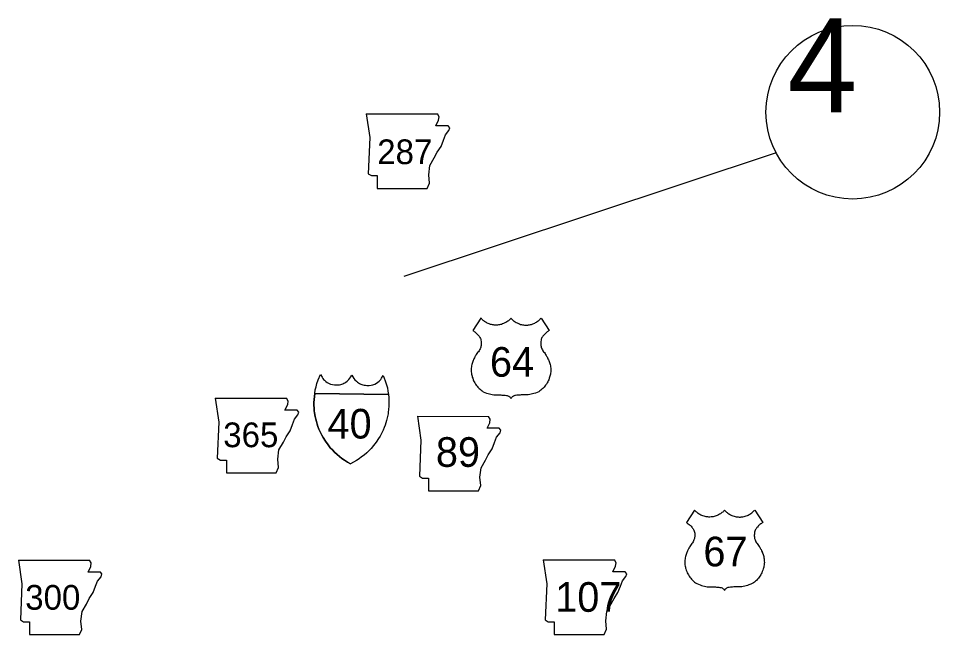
# Model space of a CAD drawing. Extents: x -819161 to 80911, y -6604 to 768454.
# Drawn here: x 43491 to 45459, y -3743 to -2427 of the extents above; entities that cross this region are included whole.
import ezdxf

# ---------------------------------------------------------------- set-up
doc = ezdxf.new("R2010")
doc.units = 0
for name, color, linetype in [('21', 7, 'Continuous'), ('22', 7, 'Continuous'), ('DSN_DRFT_Common-Line', 7, 'Continuous'), ('Level 21', 7, 'Continuous'), ('Level 22', 7, 'Continuous'), ('Level 23', 7, 'Continuous')]:
    doc.layers.add(name, color=color, linetype=linetype)

msp = doc.modelspace()

# ---------------------------------------------------------------- linework, layer by layer
at = {"layer": '21'}
for p, q in [((43490.5, -3584.4), (43498.1, -3635.2)), ((43639.4, -3609.8), (43645.3, -3598)), ((43646.2, -3590.3), (43642.6, -3584.5)), ((43645.3, -3598), (43646.2, -3590.3)), ((44611.8, -3584), (44619.5, -3634.8)), ((44760.7, -3609.4), (44766.6, -3597.6)), ((44767.5, -3589.9), (44764, -3584.1)), ((44766.6, -3597.6), (44767.5, -3589.9)), ((43665.6, -3609.8), (43639.4, -3609.8)), ((43659.7, -3629.3), (43667.3, -3620)), ((43669, -3614), (43665.6, -3609.8)), ((43667.3, -3620), (43669, -3614)), ((44786.9, -3609.4), (44760.7, -3609.4)), ((44781, -3628.9), (44788.6, -3619.6)), ((44790.3, -3613.6), (44786.9, -3609.4)), ((44788.6, -3619.6), (44790.3, -3613.6)), ((43498.1, -3635.2), (43494.7, -3712.2)), ((43650.4, -3653.8), (43655.5, -3640.3)), ((43655.5, -3640.3), (43659.7, -3629.3)), ((44619.5, -3634.8), (44616.1, -3711.8)), ((44771.7, -3653.4), (44776.8, -3639.9)), ((44776.8, -3639.9), (44781, -3628.9)), ((43641.9, -3666.5), (43650.4, -3653.8)), ((44763.3, -3666.1), (44771.7, -3653.4)), ((43626.7, -3694.4), (43636, -3678.3)), ((43636, -3678.3), (43641.9, -3666.5)), ((44748, -3694), (44757.3, -3677.9)), ((44757.3, -3677.9), (44763.3, -3666.1)), ((43624.2, -3714.7), (43626.7, -3694.4)), ((44745.5, -3714.3), (44748, -3694)), ((43494.7, -3712.2), (43501.5, -3716.4)), ((43501.5, -3716.4), (43514.2, -3716.4)), ((43514.2, -3716.4), (43514.2, -3743.5)), ((43625.9, -3732.5), (43624.2, -3714.7)), ((44616.1, -3711.8), (44622.8, -3716)), ((44622.8, -3716), (44635.5, -3716)), ((44635.5, -3716), (44635.5, -3743.1)), ((44747.2, -3732.1), (44745.5, -3714.3)), ((43620.8, -3743.5), (43625.9, -3732.5)), ((44742.1, -3743.1), (44747.2, -3732.1)), ((43514.2, -3743.5), (43620.8, -3743.5)), ((44635.5, -3743.1), (44742.1, -3743.1))]:
    msp.add_line(p, q, dxfattribs=at)
for points in [[(43490.5, -3584.4), (43642.6, -3584.5)], [(44611.8, -3584), (44764, -3584.1)]]:
    msp.add_lwpolyline(points, dxfattribs=at)
at = {"layer": '22'}
for points in [[(44999.4, -3477.5), (44998.1, -3478.9), (44996.9, -3480.2), (44995.4, -3481.6), (44993.9, -3482.9), (44992.4, -3484), (44990.6, -3485.3), (44988.7, -3486.5), (44986.5, -3487.7), (44983.7, -3489), (44981.5, -3489.9), (44979.1, -3490.6), (44976.9, -3491.2), (44974.8, -3491.6), (44972.6, -3492), (44970.7, -3492.2), (44967.9, -3492.3), (44965.7, -3492.3), (44963.8, -3492.2), (44962, -3492), (44960.1, -3491.7), (44957.8, -3491.2), (44955.6, -3490.7), (44953, -3489.8), (44950.8, -3488.9), (44948.7, -3488), (44946.9, -3487), (44945.2, -3486), (44943.2, -3484.8), (44941.5, -3483.5), (44940, -3482.2), (44938.7, -3481.1), (44937.4, -3479.8), (44936.1, -3478.5), (44935.1, -3477.3), (44917.8, -3504.1), (44919, -3504.8), (44920.5, -3505.8), (44921.9, -3506.8), (44923.7, -3508.2), (44925.2, -3509.5), (44926.6, -3510.7), (44927.9, -3512.1), (44929.3, -3513.6), (44930.2, -3514.8), (44931.2, -3516.1), (44932.2, -3517.4), (44933.2, -3518.9), (44934, -3520.6), (44934.7, -3522.7), (44935.2, -3524.7), (44935.6, -3526.9), (44935.8, -3529), (44935.9, -3531), (44935.8, -3532.8), (44935.7, -3534.3), (44935.5, -3536.1), (44935.1, -3537.9), (44934.7, -3539.7), (44934.1, -3541.3), (44933.4, -3543.2), (44932.3, -3545.5), (44931.1, -3547.4), (44929.7, -3549.1), (44928.1, -3551.2), (44926.7, -3553.1), (44925.4, -3555), (44924.2, -3556.9), (44923.2, -3558.6), (44922.4, -3560.2), (44921.4, -3562), (44920.3, -3564.2), (44919.4, -3566.4), (44918.8, -3567.9), (44918, -3570), (44917.1, -3572.5), (44916.5, -3574.5), (44915.8, -3576.8), (44915.3, -3579.4), (44914.9, -3581.8), (44914.6, -3584.2), (44914.4, -3586.9), (44914.4, -3589.4), (44914.5, -3591.8), (44914.8, -3594.7), (44915.3, -3597.4), (44915.7, -3599.5), (44916.2, -3601.3), (44916.8, -3603.3), (44917.6, -3605.9), (44918.7, -3608.9), (44919.7, -3611.2), (44920.9, -3613.6), (44922.1, -3615.8), (44923.7, -3618.5), (44925.4, -3620.9), (44927.1, -3623), (44928.9, -3625.1), (44931.3, -3627.6), (44933.3, -3629.5), (44935.4, -3631.3)], [(44999.4, -3477.5), (45000.8, -3478.9), (45002, -3480.2), (45003.4, -3481.6), (45005, -3482.9), (45006.5, -3484), (45008.3, -3485.3), (45010.2, -3486.5), (45012.4, -3487.7), (45015.2, -3489), (45017.4, -3489.9), (45019.8, -3490.6), (45022, -3491.2), (45024.1, -3491.6), (45026.2, -3492), (45028.2, -3492.2), (45030.9, -3492.3), (45033.2, -3492.3), (45035.1, -3492.2), (45036.9, -3492), (45038.8, -3491.7), (45041.1, -3491.2), (45043.3, -3490.7), (45045.9, -3489.8), (45048.1, -3488.9), (45050.1, -3488), (45052, -3487), (45053.7, -3486), (45055.6, -3484.8), (45057.4, -3483.5), (45058.9, -3482.2), (45060.2, -3481.1), (45061.5, -3479.8), (45062.8, -3478.5), (45063.8, -3477.3), (45081.1, -3504.1), (45079.9, -3504.8), (45078.4, -3505.8), (45077, -3506.8), (45075.1, -3508.2), (45073.6, -3509.5), (45072.3, -3510.7), (45071, -3512.1), (45069.6, -3513.6), (45068.6, -3514.8), (45067.7, -3516.1), (45066.7, -3517.4), (45065.7, -3518.9), (45064.8, -3520.6), (45064.2, -3522.7), (45063.6, -3524.7), (45063.3, -3526.9), (45063.1, -3529), (45063, -3531), (45063, -3532.8), (45063.2, -3534.3), (45063.4, -3536.1), (45063.7, -3537.9), (45064.2, -3539.7), (45064.7, -3541.3), (45065.5, -3543.2), (45066.6, -3545.5), (45067.7, -3547.4), (45069.1, -3549.1), (45070.8, -3551.2), (45072.2, -3553.1), (45073.5, -3555), (45074.7, -3556.9), (45075.6, -3558.6), (45076.5, -3560.2), (45077.5, -3562), (45078.5, -3564.2), (45079.5, -3566.4), (45080.1, -3567.9), (45080.9, -3570), (45081.7, -3572.5), (45082.4, -3574.5), (45083, -3576.8), (45083.6, -3579.4), (45084, -3581.8), (45084.3, -3584.2), (45084.4, -3586.9), (45084.5, -3589.4), (45084.3, -3591.8), (45084, -3594.7), (45083.6, -3597.4), (45083.1, -3599.5), (45082.7, -3601.3), (45082.1, -3603.3), (45081.3, -3605.9), (45080.1, -3608.9), (45079.2, -3611.2), (45078, -3613.6), (45076.8, -3615.8), (45075.1, -3618.5), (45073.5, -3620.9), (45071.8, -3623), (45070, -3625.1), (45067.6, -3627.6), (45065.5, -3629.5), (45063.5, -3631.3)], [(44935.4, -3631.3), (44937.6, -3632.9), (44940.2, -3634.6), (44943.5, -3636.1), (44947.3, -3637.5), (44950.4, -3638.6), (44953.3, -3639.3), (44956.4, -3640.1), (44959.4, -3640.6), (44962.6, -3641.1), (44966.7, -3641.4), (44969.8, -3641.5), (44972.4, -3641.5), (44975, -3641.5), (44977.6, -3641.6), (44980, -3641.7), (44982.2, -3641.9), (44984.3, -3642.1), (44987, -3642.3), (44989.6, -3642.7), (44991.2, -3642.9), (44992.5, -3643.1), (44994, -3643.8), (44994.9, -3644.3), (44995.7, -3644.8), (44996.8, -3645.7), (44997.8, -3646.7), (44998.7, -3647.8), (44999.4, -3649.1)], [(45063.5, -3631.3), (45061.3, -3632.9), (45058.7, -3634.6), (45055.4, -3636.1), (45051.6, -3637.5), (45048.4, -3638.6), (45045.6, -3639.3), (45042.4, -3640.1), (45039.5, -3640.6), (45036.2, -3641.1), (45032.2, -3641.4), (45029.1, -3641.5), (45026.5, -3641.5), (45023.9, -3641.5), (45021.3, -3641.6), (45018.9, -3641.7), (45016.7, -3641.9), (45014.6, -3642.1), (45011.9, -3642.3), (45009.3, -3642.7), (45007.7, -3642.9), (45006.4, -3643.1), (45004.8, -3643.8), (45003.9, -3644.3), (45003.2, -3644.8), (45002.1, -3645.7), (45001, -3646.7), (45000.2, -3647.8), (44999.4, -3649.1)]]:
    msp.add_lwpolyline(points, dxfattribs=at)
at = {"layer": 'DSN_DRFT_Common-Line'}
msp.add_lwpolyline([(45109.4, -2714.2), (44314.2, -2978.5)], dxfattribs=at)
msp.add_circle((45273.4, -2627.3), 185.5, dxfattribs=at)
at = {"layer": 'Level 21'}
for p, q in [((44233.7, -2631), (44241.3, -2681.7)), ((44389.3, -2636.9), (44385.8, -2631.1)), ((44388.5, -2644.5), (44389.3, -2636.9)), ((44382.6, -2656.4), (44388.5, -2644.5)), ((44408.8, -2656.4), (44382.6, -2656.4)), ((44412.2, -2660.6), (44408.8, -2656.4)), ((44398.6, -2686.8), (44402.9, -2675.8)), ((44402.9, -2675.8), (44410.5, -2666.5)), ((44410.5, -2666.5), (44412.2, -2660.6)), ((44241.3, -2681.7), (44237.9, -2758.7)), ((44393.6, -2700.4), (44398.6, -2686.8)), ((44379.2, -2724.9), (44385.1, -2713)), ((44385.1, -2713), (44393.6, -2700.4)), ((44369.9, -2741), (44379.2, -2724.9)), ((44367.3, -2761.3), (44369.9, -2741)), ((44237.9, -2758.7), (44244.7, -2762.9)), ((44244.7, -2762.9), (44257.4, -2762.9)), ((44257.4, -2762.9), (44257.4, -2790)), ((44369, -2779), (44367.3, -2761.3)), ((44257.4, -2790), (44363.9, -2790)), ((44363.9, -2790), (44369, -2779)), ((43911.2, -3238.5), (43918.8, -3289.3)), ((44066.8, -3244.5), (44063.3, -3238.6)), ((44066, -3252.1), (44066.8, -3244.5)), ((44060, -3263.9), (44066, -3252.1)), ((44086.3, -3263.9), (44060, -3263.9)), ((44089.6, -3268.1), (44086.3, -3263.9)), ((44076.1, -3294.4), (44080.3, -3283.4)), ((44080.3, -3283.4), (44087.9, -3274.1)), ((44087.9, -3274.1), (44089.6, -3268.1)), ((44343, -3277.1), (44350.6, -3327.9)), ((44498.7, -3283.1), (44495.1, -3277.2)), ((44497.8, -3290.7), (44498.7, -3283.1)), ((43918.8, -3289.3), (43915.4, -3366.3)), ((44071, -3307.9), (44076.1, -3294.4)), ((44491.9, -3302.5), (44497.8, -3290.7)), ((44518.1, -3302.5), (44491.9, -3302.5)), ((44521.5, -3306.8), (44518.1, -3302.5)), ((44519.8, -3312.7), (44521.5, -3306.8)), ((44056.6, -3332.4), (44062.6, -3320.6)), ((44062.6, -3320.6), (44071, -3307.9)), ((44508, -3333), (44512.2, -3322)), ((44512.2, -3322), (44519.8, -3312.7)), ((44047.3, -3348.5), (44056.6, -3332.4)), ((44350.6, -3327.9), (44347.2, -3404.9)), ((44502.9, -3346.5), (44508, -3333)), ((44044.8, -3368.8), (44047.3, -3348.5)), ((44488.5, -3371), (44494.4, -3359.2)), ((44494.4, -3359.2), (44502.9, -3346.5)), ((43915.4, -3366.3), (43922.2, -3370.5)), ((43922.2, -3370.5), (43934.8, -3370.5)), ((43934.8, -3370.5), (43934.8, -3397.6)), ((44046.5, -3386.6), (44044.8, -3368.8)), ((44479.2, -3387.1), (44488.5, -3371)), ((43934.8, -3397.6), (44041.4, -3397.6)), ((44041.4, -3397.6), (44046.5, -3386.6)), ((44347.2, -3404.9), (44354, -3409.1)), ((44476.7, -3407.4), (44479.2, -3387.1)), ((44354, -3409.1), (44366.7, -3409.1)), ((44366.7, -3409.1), (44366.7, -3436.2)), ((44478.3, -3425.2), (44476.7, -3407.4)), ((44366.7, -3436.2), (44473.3, -3436.2)), ((44473.3, -3436.2), (44478.3, -3425.2))]:
    msp.add_line(p, q, dxfattribs=at)
for points in [[(44233.7, -2631), (44385.8, -2631.1)], [(43911.2, -3238.5), (44063.3, -3238.6)], [(44343, -3277.1), (44495.1, -3277.2)]]:
    msp.add_lwpolyline(points, dxfattribs=at)
at = {"layer": 'Level 22'}
for points in [[(44543, -3067.4), (44541.7, -3068.8), (44540.5, -3070.1), (44539, -3071.5), (44537.5, -3072.8), (44536, -3074), (44534.2, -3075.2), (44532.3, -3076.4), (44530.1, -3077.6), (44527.3, -3078.9), (44525.1, -3079.8), (44522.7, -3080.6), (44520.5, -3081.1), (44518.4, -3081.6), (44516.2, -3081.9), (44514.3, -3082.1), (44511.5, -3082.2), (44509.3, -3082.2), (44507.4, -3082.1), (44505.6, -3081.9), (44503.7, -3081.6), (44501.4, -3081.1), (44499.2, -3080.6), (44496.6, -3079.7), (44494.4, -3078.8), (44492.3, -3077.9), (44490.5, -3076.9), (44488.8, -3075.9), (44486.8, -3074.7), (44485.1, -3073.4), (44483.6, -3072.1), (44482.3, -3071), (44481, -3069.8), (44479.7, -3068.4), (44478.7, -3067.2), (44461.4, -3094), (44462.6, -3094.7), (44464.1, -3095.7), (44465.5, -3096.7), (44467.3, -3098.1), (44468.8, -3099.4), (44470.1, -3100.6), (44471.5, -3102), (44472.9, -3103.5), (44473.8, -3104.7), (44474.8, -3106), (44475.8, -3107.3), (44476.8, -3108.8), (44477.6, -3110.5), (44478.3, -3112.6), (44478.8, -3114.6), (44479.2, -3116.9), (44479.4, -3118.9), (44479.5, -3120.9), (44479.4, -3122.7), (44479.3, -3124.2), (44479.1, -3126.1), (44478.7, -3127.8), (44478.3, -3129.6), (44477.7, -3131.3), (44477, -3133.1), (44475.9, -3135.4), (44474.7, -3137.3), (44473.3, -3139), (44471.7, -3141.1), (44470.3, -3143), (44469, -3145), (44467.8, -3146.8), (44466.8, -3148.5), (44466, -3150.1), (44465, -3151.9), (44463.9, -3154.1), (44463, -3156.3), (44462.3, -3157.9), (44461.6, -3159.9), (44460.7, -3162.4), (44460.1, -3164.5), (44459.4, -3166.7), (44458.9, -3169.3), (44458.5, -3171.7), (44458.2, -3174.1), (44458, -3176.8), (44458, -3179.3), (44458.1, -3181.7), (44458.4, -3184.6), (44458.9, -3187.3), (44459.3, -3189.4), (44459.8, -3191.2), (44460.4, -3193.2), (44461.2, -3195.8), (44462.3, -3198.9), (44463.3, -3201.1), (44464.5, -3203.5), (44465.7, -3205.8), (44467.3, -3208.4), (44469, -3210.8), (44470.7, -3212.9), (44472.5, -3215.1), (44474.9, -3217.5), (44476.9, -3219.4), (44479, -3221.2)], [(44543, -3067.4), (44544.4, -3068.8), (44545.6, -3070.1), (44547, -3071.5), (44548.6, -3072.8), (44550.1, -3074), (44551.9, -3075.2), (44553.8, -3076.4), (44556, -3077.6), (44558.8, -3078.9), (44561, -3079.8), (44563.4, -3080.6), (44565.6, -3081.1), (44567.7, -3081.6), (44569.8, -3081.9), (44571.8, -3082.1), (44574.5, -3082.2), (44576.8, -3082.2), (44578.7, -3082.1), (44580.5, -3081.9), (44582.4, -3081.6), (44584.7, -3081.1), (44586.9, -3080.6), (44589.5, -3079.7), (44591.7, -3078.8), (44593.7, -3077.9), (44595.6, -3076.9), (44597.3, -3075.9), (44599.2, -3074.7), (44601, -3073.4), (44602.5, -3072.1), (44603.8, -3071), (44605.1, -3069.8), (44606.3, -3068.4), (44607.4, -3067.2), (44624.7, -3094), (44623.5, -3094.7), (44622, -3095.7), (44620.6, -3096.7), (44618.7, -3098.1), (44617.2, -3099.4), (44615.9, -3100.6), (44614.6, -3102), (44613.2, -3103.5), (44612.2, -3104.7), (44611.3, -3106), (44610.3, -3107.3), (44609.3, -3108.8), (44608.4, -3110.5), (44607.8, -3112.6), (44607.2, -3114.6), (44606.9, -3116.9), (44606.7, -3118.9), (44606.6, -3120.9), (44606.6, -3122.7), (44606.8, -3124.2), (44607, -3126.1), (44607.3, -3127.8), (44607.8, -3129.6), (44608.3, -3131.3), (44609.1, -3133.1), (44610.2, -3135.4), (44611.3, -3137.3), (44612.7, -3139), (44614.4, -3141.1), (44615.8, -3143), (44617.1, -3145), (44618.3, -3146.8), (44619.2, -3148.5), (44620.1, -3150.1), (44621.1, -3151.9), (44622.1, -3154.1), (44623.1, -3156.3), (44623.7, -3157.9), (44624.5, -3159.9), (44625.3, -3162.4), (44626, -3164.5), (44626.6, -3166.7), (44627.2, -3169.3), (44627.6, -3171.7), (44627.9, -3174.1), (44628, -3176.8), (44628.1, -3179.3), (44627.9, -3181.7), (44627.6, -3184.6), (44627.2, -3187.3), (44626.7, -3189.4), (44626.3, -3191.2), (44625.7, -3193.2), (44624.9, -3195.8), (44623.7, -3198.9), (44622.8, -3201.1), (44621.6, -3203.5), (44620.4, -3205.8), (44618.7, -3208.4), (44617, -3210.8), (44615.4, -3212.9), (44613.6, -3215.1), (44611.2, -3217.5), (44609.1, -3219.4), (44607.1, -3221.2)], [(44479, -3221.2), (44481.2, -3222.8), (44483.8, -3224.5), (44487.1, -3226), (44490.9, -3227.4), (44494, -3228.5), (44496.9, -3229.2), (44500, -3230), (44503, -3230.5), (44506.2, -3231), (44510.3, -3231.3), (44513.4, -3231.4), (44516, -3231.4), (44518.6, -3231.4), (44521.2, -3231.5), (44523.6, -3231.6), (44525.8, -3231.8), (44527.9, -3232), (44530.5, -3232.2), (44533.2, -3232.6), (44534.8, -3232.8), (44536.1, -3233), (44537.6, -3233.7), (44538.5, -3234.2), (44539.3, -3234.7), (44540.4, -3235.6), (44541.4, -3236.6), (44542.3, -3237.7), (44543, -3239)], [(44607.1, -3221.2), (44604.9, -3222.8), (44602.3, -3224.5), (44599, -3226), (44595.2, -3227.4), (44592, -3228.5), (44589.2, -3229.2), (44586, -3230), (44583.1, -3230.5), (44579.8, -3231), (44575.8, -3231.3), (44572.7, -3231.4), (44570, -3231.4), (44567.5, -3231.4), (44564.9, -3231.5), (44562.4, -3231.6), (44560.3, -3231.8), (44558.2, -3232), (44555.5, -3232.2), (44552.9, -3232.6), (44551.3, -3232.8), (44550, -3233), (44548.4, -3233.7), (44547.5, -3234.2), (44546.8, -3234.7), (44545.7, -3235.6), (44544.6, -3236.6), (44543.8, -3237.7), (44543, -3239)]]:
    msp.add_lwpolyline(points, dxfattribs=at)
at = {"layer": 'Level 23'}
msp.add_line((44123.8, -3228), (44281.1, -3230.6), dxfattribs=at)
for points in [[(44123.7, -3228), (44124.9, -3220.8), (44126.5, -3214), (44128.5, -3207.3), (44131.3, -3198.8), (44136.1, -3187.7), (44139.6, -3193.7), (44141.1, -3196.2), (44142.6, -3198.2), (44144.5, -3200.1), (44147.3, -3202.6), (44150.2, -3204.7), (44153.4, -3206.5), (44157.5, -3208.1), (44161.5, -3209.2), (44165.8, -3209.8), (44170.3, -3210.1), (44173.7, -3209.8), (44176.4, -3209.6), (44179.3, -3209), (44183.4, -3207.5), (44186, -3206.4), (44188.3, -3205.3), (44190.4, -3203.9), (44193, -3201.9), (44196.5, -3198.7), (44198.9, -3195.9), (44200.9, -3192.7), (44203.1, -3189)], [(44123.7, -3228), (44124.9, -3220.8), (44126.5, -3214), (44128.5, -3207.3), (44131.3, -3198.8), (44136.1, -3187.7), (44139.6, -3193.7), (44141.1, -3196.2), (44142.6, -3198.2), (44144.5, -3200.1), (44147.3, -3202.6), (44150.2, -3204.7), (44153.4, -3206.5), (44157.5, -3208.1), (44161.5, -3209.2), (44165.8, -3209.8), (44170.3, -3210.1), (44173.7, -3209.8), (44176.4, -3209.6), (44179.3, -3209), (44183.4, -3207.5), (44186, -3206.4), (44188.3, -3205.3), (44190.4, -3203.9), (44193, -3201.9), (44196.5, -3198.7), (44198.9, -3195.9), (44200.9, -3192.7), (44203.1, -3189)], [(44203.1, -3189), (44205.2, -3192.8), (44207.1, -3196), (44209.4, -3198.9), (44212.7, -3202.3), (44215.3, -3204.3), (44217.4, -3205.8), (44219.6, -3207), (44222.2, -3208.2), (44226.3, -3209.7), (44229.2, -3210.4), (44231.9, -3210.8), (44235.2, -3211.1), (44239.7, -3211), (44244.1, -3210.5), (44248.1, -3209.6), (44252.2, -3208.1), (44255.5, -3206.4), (44258.4, -3204.3), (44261.3, -3202), (44263.2, -3200.1), (44264.8, -3198.2), (44266.4, -3195.7), (44270.1, -3189.9), (44274.5, -3201.1), (44277.1, -3209.7), (44278.9, -3216.4), (44280.2, -3223.3), (44281.2, -3230.6)], [(44203.1, -3189), (44205.2, -3192.8), (44207.1, -3196), (44209.4, -3198.9), (44212.7, -3202.3), (44215.3, -3204.3), (44217.4, -3205.8), (44219.6, -3207), (44222.2, -3208.2), (44226.3, -3209.7), (44229.2, -3210.4), (44231.9, -3210.8), (44235.2, -3211.1), (44239.7, -3211), (44244.1, -3210.5), (44248.1, -3209.6), (44252.2, -3208.1), (44255.5, -3206.4), (44258.4, -3204.3), (44261.3, -3202), (44263.2, -3200.1), (44264.8, -3198.2), (44266.4, -3195.7), (44270.1, -3189.9), (44274.5, -3201.1), (44277.1, -3209.7), (44278.9, -3216.4), (44280.2, -3223.3), (44281.2, -3230.6)], [(44200.1, -3378.3), (44193.9, -3374.9), (44187.4, -3370.8), (44181.9, -3367.1), (44176.9, -3363.3), (44171.7, -3358.9), (44166, -3353.7), (44161.3, -3349), (44157, -3344.2), (44152.2, -3338.3), (44146.4, -3330.2), (44141.7, -3322.7), (44138.7, -3317.3), (44135.7, -3311.4), (44132.8, -3304.7), (44130.6, -3299), (44128.8, -3293.7), (44127.2, -3288.4), (44125.9, -3283.2), (44124.6, -3277.6), (44123.3, -3269.6), (44122.8, -3265.4), (44122.3, -3259.7), (44122.1, -3253.1), (44122.1, -3247.5), (44122.3, -3241.2), (44122.9, -3234.5), (44123.8, -3228)], [(44123.8, -3228), (44122.9, -3234.5), (44122.3, -3241.2), (44122.1, -3247.5), (44122.1, -3253.1), (44122.3, -3259.7), (44122.8, -3265.4), (44123.3, -3269.6), (44124.6, -3277.6), (44125.9, -3283.2), (44127.2, -3288.4), (44128.8, -3293.7), (44130.6, -3299), (44132.8, -3304.7), (44135.7, -3311.4), (44138.7, -3317.3), (44141.7, -3322.7), (44146.4, -3330.2), (44152.2, -3338.3), (44157, -3344.2), (44161.3, -3349), (44166, -3353.7), (44171.7, -3358.9), (44176.9, -3363.3), (44181.9, -3367.1), (44187.4, -3370.8), (44193.9, -3374.9), (44200.1, -3378.3)], [(44281.2, -3230.6), (44123.7, -3228)], [(44281.2, -3230.6), (44123.7, -3228)], [(44281.1, -3230.6), (44281.8, -3237), (44282.1, -3243.8), (44282.2, -3250), (44282.1, -3255.7), (44281.6, -3262.3), (44280.9, -3267.9), (44280.3, -3272.1), (44278.7, -3280.1), (44277.3, -3285.7), (44275.8, -3290.7), (44274, -3296), (44272.1, -3301.2), (44269.7, -3306.9), (44266.5, -3313.5), (44263.4, -3319.3), (44260.2, -3324.6), (44255.2, -3332), (44249.2, -3339.8), (44244.2, -3345.6), (44239.7, -3350.2), (44234.9, -3354.8), (44229.1, -3359.8), (44223.7, -3364), (44218.6, -3367.7), (44213, -3371.2), (44206.4, -3375.1), (44200.1, -3378.3)], [(44281.1, -3230.6), (44281.8, -3237), (44282.1, -3243.8), (44282.2, -3250), (44282.1, -3255.7), (44281.6, -3262.3), (44280.9, -3267.9), (44280.3, -3272.1), (44278.7, -3280.1), (44277.3, -3285.7), (44275.8, -3290.7), (44274, -3296), (44272.1, -3301.2), (44269.7, -3306.9), (44266.5, -3313.5), (44263.4, -3319.3), (44260.2, -3324.6), (44255.2, -3332), (44249.2, -3339.8), (44244.2, -3345.6), (44239.7, -3350.2), (44234.9, -3354.8), (44229.1, -3359.8), (44223.7, -3364), (44218.6, -3367.7), (44213, -3371.2), (44206.4, -3375.1), (44200.1, -3378.3)]]:
    msp.add_lwpolyline(points, dxfattribs=at)

# ---------------------------------------------------------------- texts
at = {"layer": '21'}
for s, height, p in [('300', 52.8, (43505, -3690.3)), ('107', 63.36, (44637.6, -3694.8))]:
    msp.add_text(s, height=height, dxfattribs=at).set_placement(p)
at = {"layer": '22'}
msp.add_text('67', height=63.36, dxfattribs=at).set_placement((44954.2, -3597.7))
at = {"layer": 'DSN_DRFT_Common-Line'}
msp.add_text('4', height=200.4, dxfattribs=at).set_placement((45133.9, -2627.3))
at = {"layer": 'Level 21'}
for s, height, p in [('287', 52.8, (44257.2, -2738.3)), ('365', 52.8, (43928.2, -3343.1)), ('89', 63.36, (44382.6, -3385.1))]:
    msp.add_text(s, height=height, dxfattribs=at).set_placement(p)
at = {"layer": 'Level 22'}
msp.add_text('64', height=63.36, dxfattribs=at).set_placement((44498.1, -3192.5))
at = {"layer": 'Level 23'}
msp.add_text('40', height=63.36, dxfattribs=at).set_placement((44151, -3324.6))

doc.saveas('drawing.dxf')
